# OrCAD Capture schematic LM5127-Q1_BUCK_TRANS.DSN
size Custom; title: LM5127-Q1 2.2MHz Wide VIN Automotive Front-stage; rev: 1.0; note: Datasheet: NA     EVM: NA; note: Synchronous Step Down Converter
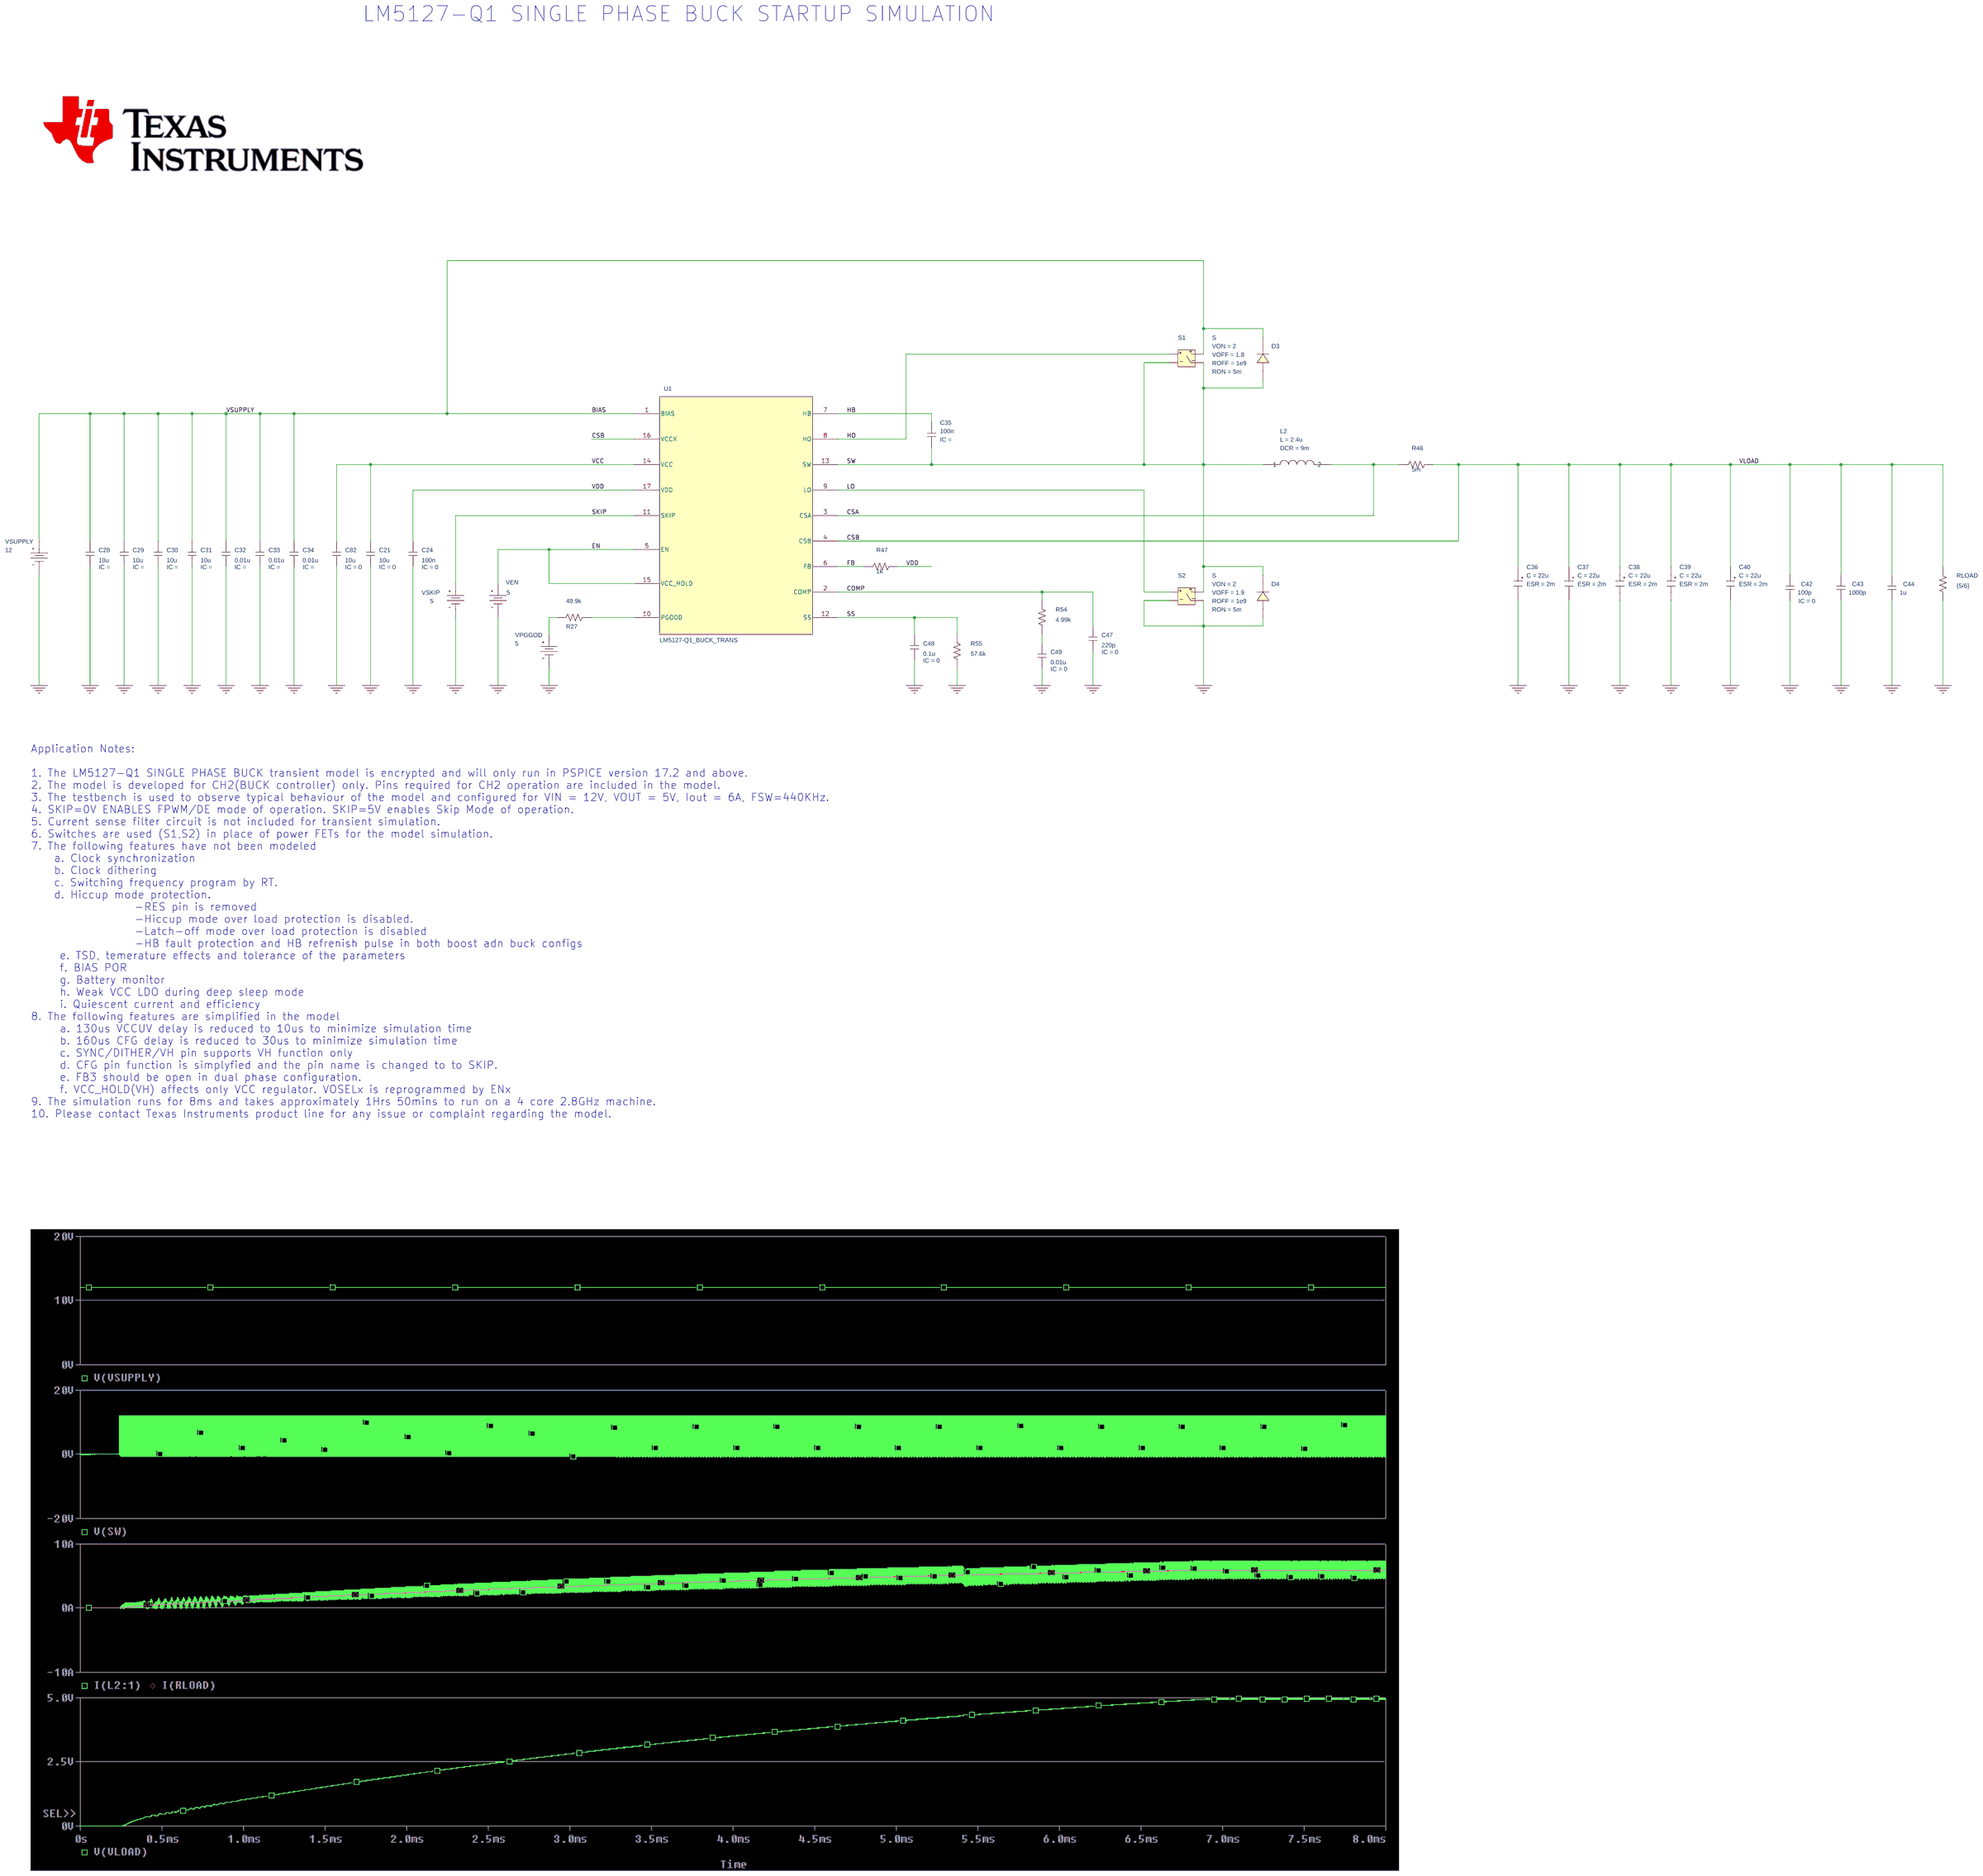
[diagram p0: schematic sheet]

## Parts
C21  10u  [RAD/CK05]
C24  100n  [RAD/CK05]
C28  10u  [RAD/CK05]
C29  10u  [RAD/CK05]
C30  10u  [RAD/CK05]
C31  10u  [RAD/CK05]
C32  0.01u  [RAD/CK05]
C33  0.01u  [RAD/CK05]
C34  0.01u  [RAD/CK05]
C35  100n  [RAD/CK05]
C36  CESR
C37  CESR
C38  CESR
C39  CESR
C40  CESR
C42  100p  [RAD/CK05]
C43  1000p  [RAD/CK05]
C44  1u  [RAD/CK05]
C47  220p  [RAD/CK05]
C48  0.1u  [RAD/CK05]
C49  0.01u  [RAD/CK05]
C82  10u  [RAD/CK05]
D3  D_D1
D4  D_D1
L2  LDCR
R27  49.9k  [AX/RC05]
R46  5m  [AX/RC05]
R47  1k  [AX/RC05]
R54  4.99k  [AX/RC05]
R55  57.6k  [AX/RC05]
RLOAD  {5/6}  [AX/RC05]
S1  S
S2  S
U1  LM5127-Q1_BUCK_TRANS
VEN  VDC
VPGGOD  VDC
VSKIP  VDC
VSUPPLY  VDC

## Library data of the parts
C21 C24 C42 C47-C49 C82 = C: IC: 0
C28-C35 C43 C44 = C
C36-C40 = CESR_0: C: 22u; ESR: 2m; PSpiceTemplate: X^@REFDES %IN %OUT @MODEL PARAMS:  ?C|C=@C||C=100u|  ?ESR|ESR=@ESR||ESR=0.01|; X: 1
D3 D4 = D_D1
L2 = LDCR: DCR: 9m; L: 2.4u
R27 R46 R47 R54 R55 RLOAD = R
S1 = S: ROFF: 1e9; RON: 5m; VOFF: 1.8; VON: 2
S2 = S: ROFF: 1e9; RON: 5m; VOFF: 1.9; VON: 2
U1 = LM5127-Q1_BUCK_TRANS
VEN VPGGOD VSKIP = VDC: DC: 5
VSUPPLY = VDC: DC: 12

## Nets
VCC: C21.2 C82.2 U1.14(VCC)
VDD: C24.2 R47.2 U1.17(VDD)
0: C21.1 C24.1 C28.1 C29.1 C30.1 C31.1 C32.1 C33.1 C34.1 C36.2(OUT) C37.2(OUT) C38.2(OUT) C39.2(OUT) C40.2(OUT) C42.2 C43.2 C44.2 C47.1 C48.1 C49.1 C82.1 D4.2(A) R55.1 RLOAD.2 S2.1(2) S2.3(4) VEN.1(-) VPGGOD.1(-) VSKIP.1(-) VSUPPLY.1(-)
BIAS: C28.2 C29.2 C30.2 C31.2 C32.2 C33.2 C34.2 D3.1(C) S1.2(3) U1.1(BIAS) VSUPPLY.0(+)
COMP: C47.2 R54.2 U1.2(COMP)
CSA: L2.2 R46.1 U1.3(CSA)
CSB: C36.1(IN) C37.1(IN) C38.1(IN) C39.1(IN) C40.1(IN) C42.1 C43.1 C44.1 R46.2 RLOAD.1 U1.4(CSB) U1.16(VCCX)
EN: U1.5(EN) U1.15(VCC_HOLD) VEN.0(+)
FB: R47.1 U1.6(FB)
HB: C35.2 U1.7(HB)
HO: S1.0(1) U1.8(HO)
LO: S2.0(1) U1.9(LO)
SKIP: U1.11(SKIP) VSKIP.0(+)
SS: C48.2 R55.2 U1.12(SS)
SW: C35.1 D3.2(A) D4.1(C) L2.1 S1.1(2) S1.3(4) S2.2(3) U1.13(SW)
N54488: R27.2 VPGGOD.0(+)
N54610: R27.1 U1.10(PGOOD)
N63177: C49.2 R54.1

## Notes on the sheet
- LM5127-Q1 SINGLE PHASE BUCK STARTUP SIMULATION
- Application Notes:
  1. The LM5127-Q1 SINGLE PHASE BUCK transient model is encrypted and will only run in PSPICE version 17.2 and above.
  2. The model is developed for CH2(BUCK controller) only. Pins required for CH2 operation are included in the model.
  3. The testbench is used to observe typical behaviour of the model and configured for VIN = 12V, VOUT = 5V, Iout = 6A, FSW=440KHz.
  4. SKIP=0V ENABLES FPWM/DE mode of operation. SKIP=5V enables Skip Mode of operation.
  5. Current sense filter circuit is not included for transient simulation.
  6. Switches are used (S1,S2) in place of power FETs for the model simulation.
  7. The following features have not been modeled
      a. Clock synchronization
      b. Clock dithering
      c. Switching frequency program by RT.
      d. Hiccup mode protection.
                    -RES pin is removed
                    -Hiccup mode over load protection is disabled.
                    -Latch-off mode over load protection is disabled
                    -HB fault protection and HB refrenish pulse in both boost adn buck configs
       e. TSD, temerature effects and tolerance of the parameters
       f. BIAS POR
       g. Battery monitor
       h. Weak VCC LDO during deep sleep mode
       i. Quiescent current and efficiency
  8. The following features are simplified in the model
       a. 130us VCCUV delay is reduced to 10us to minimize simulation time
       b. 160us CFG delay is reduced to 30us to minimize simulation time
       c. SYNC/DITHER/VH pin supports VH function only
       d. CFG pin function is simplyfied and the pin name is changed to to SKIP.
       e. FB3 should be open in dual phase configuration.
       f. VCC_HOLD(VH) affects only VCC regulator. VOSELx is reprogrammed by ENx
  9. The simulation runs for 8ms and takes approximately 1Hrs 50mins to run on a 4 core 2.8GHz machine.
  10. Please contact Texas Instruments product line for any issue or complaint regarding the model.
